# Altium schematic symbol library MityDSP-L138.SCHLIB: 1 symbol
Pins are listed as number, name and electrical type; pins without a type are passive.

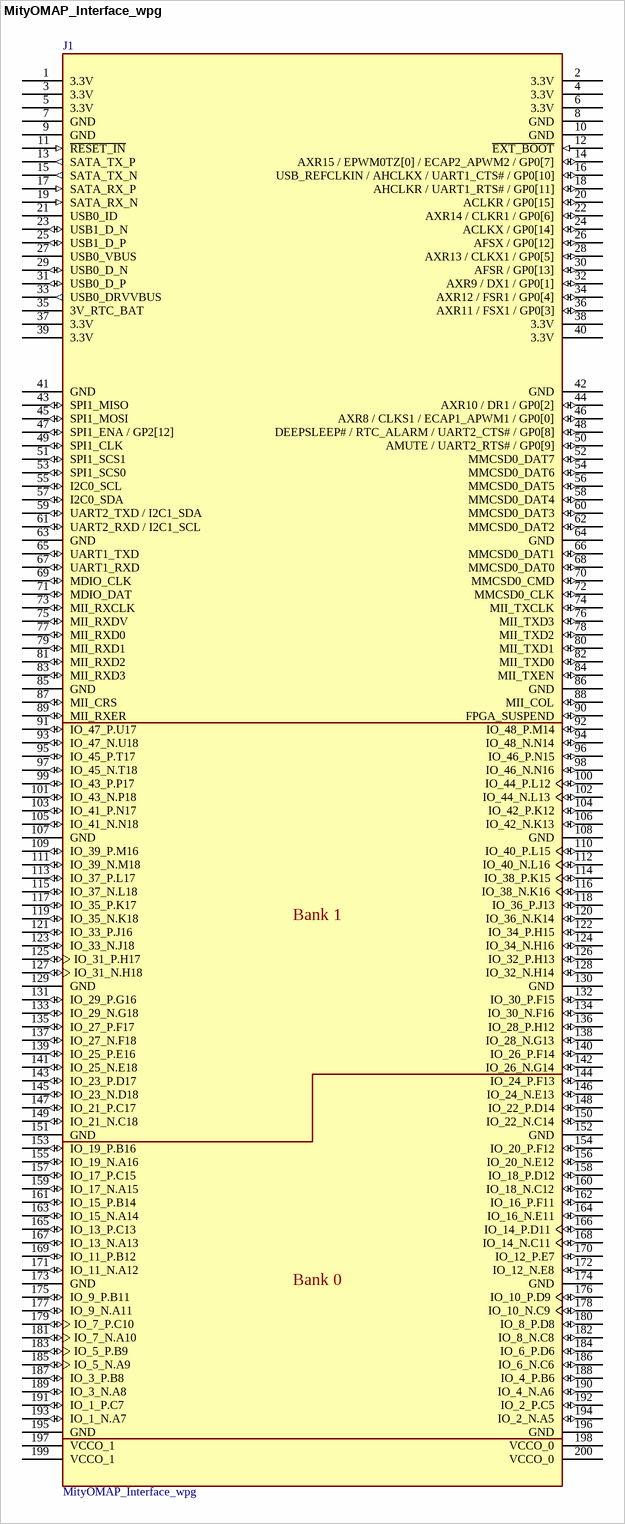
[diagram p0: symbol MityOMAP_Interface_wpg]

## MityOMAP_Interface_wpg
designator J1
CONN SODIMM DDR2 200POS R/A SMD W_PEG; User: Alexei; Dist1: Digi-Key; Dist1_PN: 609-1007-ND; Mfg: Tyco Electronics; Mfg_PID: 3024; Mfg_PN: 10033853-052FSLF
footprint DDR2_Edge
footprint 10033853-152FSLF (CONN SODIMM DDR2 200POS R/A SMD)
pins: 1 3.3V (power), 2 3.3V (power), 3 3.3V (power), 4 3.3V (power), 5 3.3V (power), 6 3.3V (power), 7 GND (power), 8 GND (power), 9 GND (power), 10 GND (power), 11 ~{RESET_IN} (in), 12 ~{EXT_BOOT} (in), 13 SATA_TX_P (out), 14 AXR15 / EPWM0TZ[0] / ECAP2_APWM2 / GP0[7] (io) "Pull=CP[1] / PwrGrp=A", 15 SATA_TX_N (out), 16 USB_REFCLKIN / AHCLKX / UART1_CTS# / GP0[10] (io) "Pull=CP[0] / PwrGrp=A", 17 SATA_RX_P (in), 18 AHCLKR / UART1_RTS# / GP0[11] (io) "Pull=CP[0] / PwrGrp=A", 19 SATA_RX_N (in), 20 ACLKR / GP0[15] (io) "Pull=CP[0] / PwrGrp=A", 21 USB0_ID, 22 AXR14 / CLKR1 / GP0[6] (io) "Pull=CP[2] / PwrGrp=A", 23 USB1_D_N (io), 24 ACLKX / GP0[14] (io) "Pull=CP[0] / PwrGrp=A", 25 USB1_D_P (io), 26 AFSX / GP0[12] (io) "Pull=CP[0] / PwrGrp=A", 27 USB0_VBUS, 28 AXR13 / CLKX1 / GP0[5] (io) "Pull=CP[2] / PwrGrp=A", 29 USB0_D_N (io), 30 AFSR / GP0[13] (io) "Pull=CP[0] / PwrGrp=A", 31 USB0_D_P (io), 32 AXR9 / DX1 / GP0[1] (io) "Pull=CP[2] / PwrGrp=A", 33 USB0_DRVVBUS (out), 34 AXR12 / FSR1 / GP0[4] (io) "Pull=CP[2] / PwrGrp=A", 35 3V_RTC_BAT (power), 36 AXR11 / FSX1 / GP0[3] (io) "Pull=CP[2] / PwrGrp=A", 37 3.3V (power), 38 3.3V (power), 39 3.3V (power), 40 3.3V (power), 41 GND (power), 42 GND (power), 43 SPI1_MISO (io), 44 AXR10 / DR1 / GP0[2] (io) "Pull=CP[2] / PwrGrp=A", 45 SPI1_MOSI (io), 46 AXR8 / CLKS1 / ECAP1_APWM1 / GP0[0] (io) "Pull=CP[3] / PwrGrp=A", 47 SPI1_ENA / GP2[12] (io), 48 DEEPSLEEP# / RTC_ALARM / UART2_CTS# / GP0[8] (io) "Pull=CP[0] / PwrGrp=A", 49 SPI1_CLK (io), 50 AMUTE / UART2_RTS# / GP0[9] (io) "Pull=CP[0] / PwrGrp=A", 51 SPI1_SCS1 (io), 52 MMCSD0_DAT7 (io), 53 SPI1_SCS0 (io), 54 MMCSD0_DAT6 (io), 55 I2C0_SCL (io), 56 MMCSD0_DAT5 (io), 57 I2C0_SDA (io), 58 MMCSD0_DAT4 (io), 59 UART2_TXD / I2C1_SDA (io), 60 MMCSD0_DAT3 (io), 61 UART2_RXD / I2C1_SCL (io), 62 MMCSD0_DAT2 (io), 63 GND (power), 64 GND (power), 65 UART1_TXD (io), 66 MMCSD0_DAT1 (io), 67 UART1_RXD (io), 68 MMCSD0_DAT0 (io), 69 MDIO_CLK (io), 70 MMCSD0_CMD (io), 71 MDIO_DAT (io), 72 MMCSD0_CLK (io), 73 MII_RXCLK (io), 74 MII_TXCLK (io), 75 MII_RXDV (io), 76 MII_TXD3 (io), 77 MII_RXD0 (io), 78 MII_TXD2 (io), 79 MII_RXD1 (io), 80 MII_TXD1 (io), 81 MII_RXD2 (io), 82 MII_TXD0 (io), 83 MII_RXD3 (io), 84 MII_TXEN (io), 85 GND (power), 86 GND (power), 87 MII_CRS (io), 88 MII_COL (io), 89 MII_RXER (io), 90 FPGA_SUSPEND (io), 91 IO_47_P.U17 (io), 92 IO_48_P.M14 (io), 93 IO_47_N.U18 (io), 94 IO_48_N.N14 (io), 95 IO_45_P.T17 (io), 96 IO_46_P.N15 (io), 97 IO_45_N.T18 (io), 98 IO_46_N.N16 (io), 99 IO_43_P.P17 (io), 100 IO_44_P.L12 (io), 101 IO_43_N.P18 (io), 102 IO_44_N.L13 (io), 103 IO_41_P.N17 (io), 104 IO_42_P.K12 (io), 105 IO_41_N.N18 (io), 106 IO_42_N.K13 (io), 107 GND (power), 108 GND (power), 109 IO_39_P.M16 (io), 110 IO_40_P.L15 (io), 111 IO_39_N.M18 (io), 112 IO_40_N.L16 (io), 113 IO_37_P.L17 (io), 114 IO_38_P.K15 (io), 115 IO_37_N.L18 (io), 116 IO_38_N.K16 (io), 117 IO_35_P.K17 (io), 118 IO_36_P.J13 (io), 119 IO_35_N.K18 (io), 120 IO_36_N.K14 (io), 121 IO_33_P.J16 (io), 122 IO_34_P.H15 (io), 123 IO_33_N.J18 (io), 124 IO_34_N.H16 (io), 125 IO_31_P.H17 (io), 126 IO_32_P.H13 (io), 127 IO_31_N.H18 (io), 128 IO_32_N.H14 (io), 129 GND (power), 130 GND (power), 131 IO_29_P.G16 (io), 132 IO_30_P.F15 (io), 133 IO_29_N.G18 (io), 134 IO_30_N.F16 (io), 135 IO_27_P.F17 (io), 136 IO_28_P.H12 (io), 137 IO_27_N.F18 (io), 138 IO_28_N.G13 (io), 139 IO_25_P.E16 (io), 140 IO_26_P.F14 (io), 141 IO_25_N.E18 (io), 142 IO_26_N.G14 (io), 143 IO_23_P.D17 (io), 144 IO_24_P.F13 (io), 145 IO_23_N.D18 (io), 146 IO_24_N.E13 (io), 147 IO_21_P.C17 (io), 148 IO_22_P.D14 (io), 149 IO_21_N.C18 (io), 150 IO_22_N.C14 (io), 151 GND (power), 152 GND (power), 153 IO_19_P.B16 (io), 154 IO_20_P.F12 (io), 155 IO_19_N.A16 (io), 156 IO_20_N.E12 (io), 157 IO_17_P.C15 (io), 158 IO_18_P.D12 (io), 159 IO_17_N.A15 (io), 160 IO_18_N.C12 (io), 161 IO_15_P.B14 (io), 162 IO_16_P.F11 (io), 163 IO_15_N.A14 (io), 164 IO_16_N.E11 (io), 165 IO_13_P.C13 (io), 166 IO_14_P.D11 (io), 167 IO_13_N.A13 (io), 168 IO_14_N.C11 (io), 169 IO_11_P.B12 (io), 170 IO_12_P.E7 (io), 171 IO_11_N.A12 (io), 172 IO_12_N.E8 (io), 173 GND (power), 174 GND (power), 175 IO_9_P.B11 (io), 176 IO_10_P.D9 (io), 177 IO_9_N.A11 (io), 178 IO_10_N.C9 (io), 179 IO_7_P.C10 (io), 180 IO_8_P.D8 (io), 181 IO_7_N.A10 (io), 182 IO_8_N.C8 (io), 183 IO_5_P.B9 (io), 184 IO_6_P.D6 (io), 185 IO_5_N.A9 (io), 186 IO_6_N.C6 (io), 187 IO_3_P.B8 (io), 188 IO_4_P.B6 (io), 189 IO_3_N.A8 (io), 190 IO_4_N.A6 (io), 191 IO_1_P.C7 (io), 192 IO_2_P.C5 (io), 193 IO_1_N.A7 (io), 194 IO_2_N.A5 (io), 195 GND (power), 196 GND (power), 197 VCCO_1 (power), 198 VCCO_0 (power), 199 VCCO_1 (power), 200 VCCO_0 (power)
